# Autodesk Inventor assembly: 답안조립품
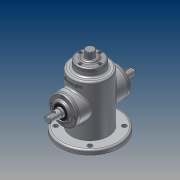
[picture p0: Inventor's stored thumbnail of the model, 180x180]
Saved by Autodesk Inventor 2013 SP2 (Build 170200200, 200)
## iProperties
Created: 2014-12
Part Number: 답안조립품
Document SubType Name: Assembly
Designer: CADB302
Author: CADB302
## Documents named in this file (12)
- C:\Users\CADB302\Desktop\441228V1019\답안조립품.iam
- C:\Users\CADB302\Desktop\441228V1019\본체.ipt
- C:\Users\CADB302\Desktop\441228V1019\베어링 6002.ipt
- 베어링 6002.ipt
- C:\Users\CADB302\Desktop\441228V1019\편심축.ipt
- C:\Users\CADB302\Desktop\441228V1019\커버.ipt
- C:\Users\CADB302\Desktop\441228V1019\오일실.ipt
- 오일실.ipt
- C:\Users\CADB302\Desktop\441228V1019\슬라이드.ipt
- C:\Users\CADB302\Desktop\441228V1019\상단커버.ipt
- C:\Users\CADB302\Desktop\441228V1019\M3x0.5x8.ipt
- M3x0.5.ipt
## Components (12 placed, 1 different names)
1. M3x0.5:1 — 각도:2
2. M3x0.5:4
3. M3x0.5:5
4. M3x0.5:6
5. M3x0.5:2 — 각도:3
6. M3x0.5:7
7. M3x0.5:8
8. M3x0.5:9
9. M3x0.5:3 — 각도:4
10. M3x0.5:10
11. M3x0.5:11
12. M3x0.5:12
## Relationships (3: Angle 3)
- 각도:2 [Angle]: M3x0.5:1
- 각도:3 [Angle]: M3x0.5:2
- 각도:4 [Angle]: M3x0.5:3
